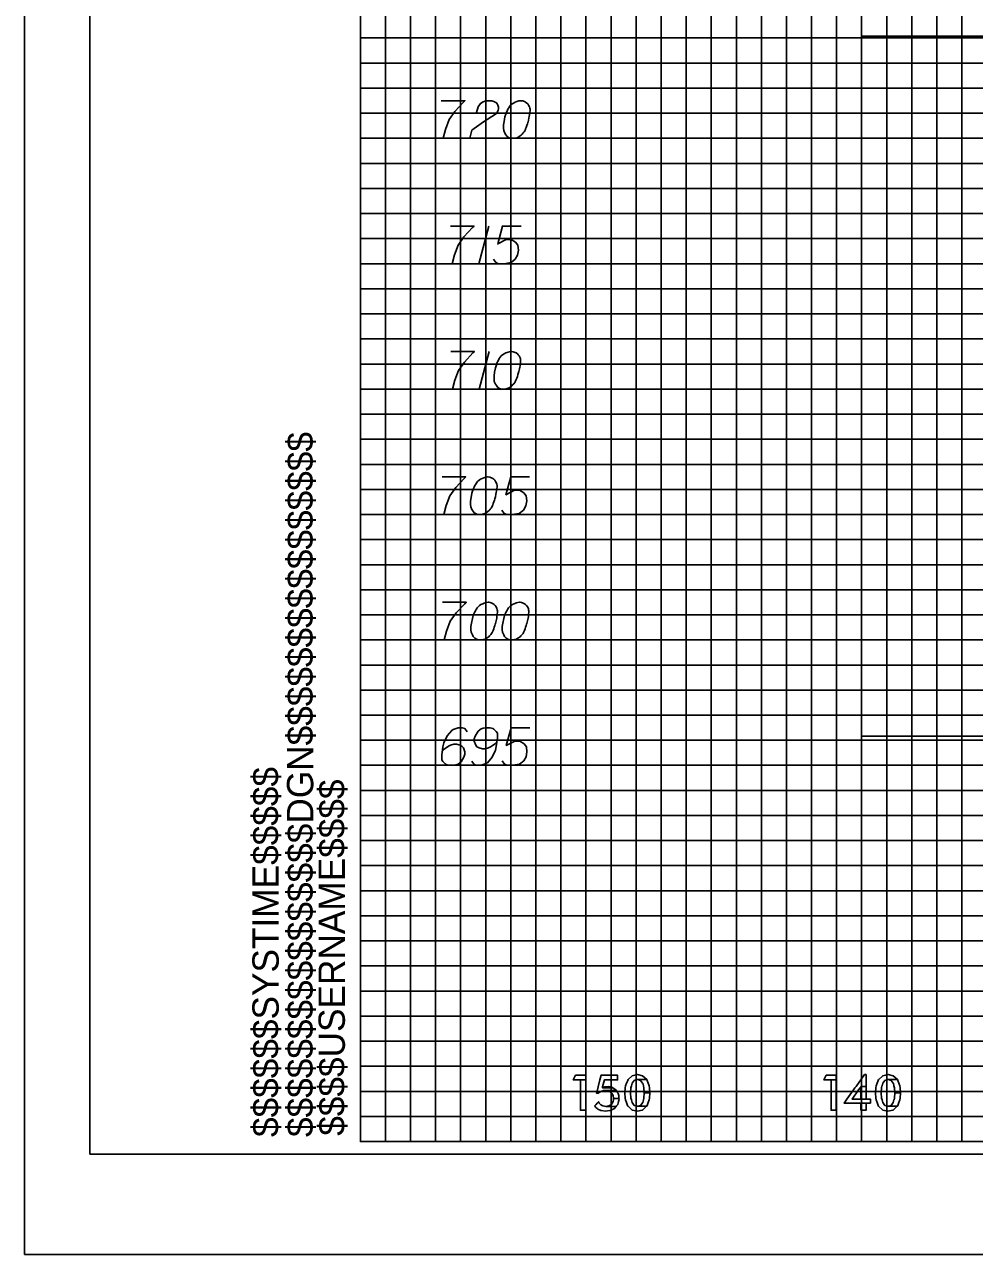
# Model space of a CAD drawing. Extents: x -13 to 323, y -5 to 1431.
# Drawn here: x -13.4 to 24.5, y 655.5 to 704.53 of the extents above; entities that cross this region are included whole.
import ezdxf

# ---------------------------------------------------------------- set-up
doc = ezdxf.new("R2010")
doc.units = 0
for name, color, linetype in [('Prop XS Elevation Labels', 7, 'Continuous'), ('Prop XS Offset Labels', 7, 'Continuous'), ('Scratch_Level_3', 7, 'Continuous'), ('Sheet Cross Section CELL', 7, 'Continuous'), ('Sheet Cross Section Grid Major CELL', 7, 'Continuous'), ('Sheet Cross Section Grid Middle CELL', 7, 'Continuous'), ('Sheet Cross Section Grid Minor 1 CELL', 7, 'Continuous'), ('Sheet Cross Section Grid Minor 2 CELL', 7, 'Continuous'), ('Sheet Cutting Line CELL', 7, 'Continuous'), ('Sheet DOT Grid CELL', 7, 'Continuous'), ('Sheet Plot Border Inside CELL', 7, 'Continuous'), ('Sheet Plot Border Outside CELL', 7, 'Continuous')]:
    doc.layers.add(name, color=color, linetype=linetype)

msp = doc.modelspace()

# ---------------------------------------------------------------- linework, layer by layer
at = {"layer": 'Prop XS Elevation Labels'}
for p, q in [((5.124, 696.5), (4.723, 695)), ((5.142, 691.5), (4.74, 690))]:
    msp.add_line(p, q, dxfattribs=at)
for points in [[(3.228, 701.5), (4.173, 701.5), (4.114, 701.441), (3.772, 701.075), (3.535, 700.744), (3.394, 700.354), (3.299, 700)], [(4.634, 701.028), (4.693, 701.252), (4.787, 701.394), (4.894, 701.453), (5, 701.488), (5.083, 701.5), (5.142, 701.5), (5.248, 701.488), (5.319, 701.465), (5.354, 701.453), (5.425, 701.417), (5.461, 701.37), (5.484, 701.323), (5.496, 701.287), (5.508, 701.24), (5.508, 701.181), (5.496, 701.122), (5.484, 701.087), (5.461, 701.039), (5.425, 700.992), (5.39, 700.957), (4.906, 700.661), (4.445, 700.319), (4.362, 700), (5.437, 700)], [(6.417, 701.5), (6.394, 701.5), (6.323, 701.488), (6.276, 701.476), (6.24, 701.465), (6.181, 701.441), (6.11, 701.406), (6.051, 701.37), (5.992, 701.323), (5.957, 701.276), (5.921, 701.217), (5.886, 701.158), (5.85, 701.087), (5.827, 701.039), (5.803, 700.969), (5.768, 700.85), (5.732, 700.673), (5.709, 700.531), (5.709, 700.402), (5.721, 700.307), (5.768, 700.201), (5.803, 700.142), (5.862, 700.071), (5.933, 700.024), (5.968, 700.012), (6.039, 700), (6.098, 700), (6.193, 700.012), (6.276, 700.035), (6.335, 700.071), (6.417, 700.13), (6.453, 700.165), (6.5, 700.213), (6.535, 700.26), (6.559, 700.295), (6.583, 700.354), (6.594, 700.378), (6.618, 700.437), (6.642, 700.508), (6.665, 700.579), (6.677, 700.626), (6.689, 700.661), (6.701, 700.709), (6.724, 700.815), (6.736, 700.874), (6.748, 700.933), (6.76, 701.016), (6.772, 701.122), (6.772, 701.158), (6.76, 701.205), (6.748, 701.252), (6.713, 701.323), (6.677, 701.37), (6.642, 701.406), (6.594, 701.441), (6.547, 701.465), (6.512, 701.476), (6.476, 701.488), (6.417, 701.5)], [(3.589, 696.5), (4.533, 696.5), (4.474, 696.441), (4.132, 696.075), (3.896, 695.744), (3.754, 695.354), (3.659, 695)], [(6.411, 696.5), (5.667, 696.5), (5.478, 695.791), (5.821, 695.969), (6.022, 695.969), (6.187, 695.862), (6.282, 695.744), (6.305, 695.543), (6.27, 695.342), (6.175, 695.177), (6.01, 695.047), (5.726, 695), (5.514, 695), (5.408, 695.047), (5.313, 695.177)], [(3.606, 691.5), (4.551, 691.5), (4.492, 691.441), (4.149, 691.075), (3.913, 690.744), (3.772, 690.354), (3.677, 690)], [(6.039, 691.5), (6.016, 691.5), (5.945, 691.488), (5.898, 691.476), (5.862, 691.465), (5.803, 691.441), (5.732, 691.406), (5.673, 691.37), (5.614, 691.323), (5.579, 691.276), (5.543, 691.217), (5.508, 691.158), (5.472, 691.087), (5.449, 691.039), (5.425, 690.969), (5.39, 690.85), (5.354, 690.673), (5.331, 690.531), (5.331, 690.402), (5.343, 690.307), (5.39, 690.201), (5.425, 690.142), (5.484, 690.071), (5.555, 690.024), (5.591, 690.012), (5.661, 690), (5.72, 690), (5.815, 690.012), (5.898, 690.035), (5.957, 690.071), (6.039, 690.13), (6.075, 690.165), (6.122, 690.213), (6.157, 690.26), (6.181, 690.295), (6.205, 690.354), (6.217, 690.378), (6.24, 690.437), (6.264, 690.508), (6.287, 690.579), (6.299, 690.626), (6.311, 690.661), (6.323, 690.709), (6.347, 690.815), (6.358, 690.874), (6.37, 690.933), (6.382, 691.016), (6.394, 691.122), (6.394, 691.158), (6.382, 691.205), (6.37, 691.252), (6.335, 691.323), (6.299, 691.37), (6.264, 691.406), (6.217, 691.441), (6.169, 691.465), (6.134, 691.476), (6.098, 691.488), (6.039, 691.5)], [(3.258, 686.5), (4.203, 686.5), (4.144, 686.441), (3.801, 686.075), (3.565, 685.744), (3.423, 685.354), (3.329, 685)], [(5.1, 686.5), (5.077, 686.5), (5.006, 686.488), (4.959, 686.476), (4.923, 686.465), (4.864, 686.441), (4.793, 686.406), (4.734, 686.37), (4.675, 686.323), (4.64, 686.276), (4.604, 686.217), (4.569, 686.158), (4.534, 686.087), (4.51, 686.039), (4.486, 685.969), (4.451, 685.85), (4.415, 685.673), (4.392, 685.531), (4.392, 685.402), (4.404, 685.307), (4.451, 685.201), (4.486, 685.142), (4.545, 685.071), (4.616, 685.024), (4.652, 685.012), (4.723, 685), (4.781, 685), (4.876, 685.012), (4.959, 685.035), (5.018, 685.071), (5.1, 685.13), (5.136, 685.165), (5.183, 685.213), (5.219, 685.26), (5.242, 685.295), (5.266, 685.354), (5.278, 685.378), (5.301, 685.437), (5.325, 685.508), (5.349, 685.579), (5.36, 685.626), (5.372, 685.661), (5.384, 685.709), (5.408, 685.815), (5.419, 685.874), (5.431, 685.933), (5.443, 686.016), (5.455, 686.122), (5.455, 686.158), (5.443, 686.205), (5.431, 686.252), (5.396, 686.323), (5.36, 686.37), (5.325, 686.406), (5.278, 686.441), (5.23, 686.465), (5.195, 686.476), (5.16, 686.488), (5.1, 686.5)], [(6.742, 686.5), (5.998, 686.5), (5.809, 685.791), (6.152, 685.969), (6.352, 685.969), (6.518, 685.862), (6.612, 685.744), (6.636, 685.543), (6.6, 685.342), (6.506, 685.177), (6.341, 685.047), (6.057, 685), (5.845, 685), (5.738, 685.047), (5.644, 685.177)], [(3.276, 681.5), (4.22, 681.5), (4.161, 681.441), (3.819, 681.075), (3.583, 680.744), (3.441, 680.354), (3.346, 680)], [(5.118, 681.5), (5.094, 681.5), (5.024, 681.488), (4.977, 681.476), (4.941, 681.465), (4.882, 681.441), (4.811, 681.406), (4.752, 681.37), (4.693, 681.323), (4.658, 681.276), (4.622, 681.217), (4.587, 681.158), (4.551, 681.087), (4.528, 681.039), (4.504, 680.969), (4.469, 680.85), (4.433, 680.673), (4.409, 680.531), (4.409, 680.402), (4.421, 680.307), (4.469, 680.201), (4.504, 680.142), (4.563, 680.071), (4.634, 680.024), (4.669, 680.012), (4.74, 680), (4.799, 680), (4.894, 680.012), (4.977, 680.035), (5.036, 680.071), (5.118, 680.13), (5.154, 680.165), (5.201, 680.213), (5.236, 680.26), (5.26, 680.295), (5.283, 680.354), (5.295, 680.378), (5.319, 680.437), (5.342, 680.508), (5.366, 680.579), (5.378, 680.626), (5.39, 680.661), (5.402, 680.709), (5.425, 680.815), (5.437, 680.874), (5.449, 680.933), (5.461, 681.016), (5.473, 681.122), (5.473, 681.158), (5.461, 681.205), (5.449, 681.252), (5.413, 681.323), (5.378, 681.37), (5.342, 681.406), (5.295, 681.441), (5.248, 681.465), (5.213, 681.476), (5.177, 681.488), (5.118, 681.5)], [(6.37, 681.5), (6.346, 681.5), (6.276, 681.488), (6.228, 681.476), (6.193, 681.465), (6.134, 681.441), (6.063, 681.406), (6.004, 681.37), (5.945, 681.323), (5.909, 681.276), (5.874, 681.217), (5.838, 681.158), (5.803, 681.087), (5.779, 681.039), (5.756, 680.969), (5.721, 680.85), (5.685, 680.673), (5.661, 680.531), (5.661, 680.402), (5.673, 680.307), (5.721, 680.201), (5.756, 680.142), (5.815, 680.071), (5.886, 680.024), (5.921, 680.012), (5.992, 680), (6.051, 680), (6.146, 680.012), (6.228, 680.035), (6.287, 680.071), (6.37, 680.13), (6.406, 680.165), (6.453, 680.213), (6.488, 680.26), (6.512, 680.295), (6.535, 680.354), (6.547, 680.378), (6.571, 680.437), (6.594, 680.508), (6.618, 680.579), (6.63, 680.626), (6.642, 680.661), (6.653, 680.709), (6.677, 680.815), (6.689, 680.874), (6.701, 680.933), (6.713, 681.016), (6.724, 681.122), (6.724, 681.158), (6.713, 681.205), (6.701, 681.252), (6.665, 681.323), (6.63, 681.37), (6.594, 681.406), (6.547, 681.441), (6.5, 681.465), (6.464, 681.476), (6.429, 681.488), (6.37, 681.5)], [(4.262, 676.335), (4.168, 676.465), (4.061, 676.5), (3.896, 676.5), (3.778, 676.453), (3.707, 676.429), (3.648, 676.394), (3.459, 676.181), (3.329, 675.898), (3.294, 675.744), (3.246, 675.402), (3.246, 675.224), (3.294, 675.154), (3.388, 675.059), (3.423, 675.035), (3.542, 675), (3.695, 675), (3.813, 675.024), (3.896, 675.047), (4.014, 675.142), (4.132, 675.331), (4.168, 675.449), (4.168, 675.543), (4.109, 675.697), (4.061, 675.756), (3.979, 675.803), (3.837, 675.839), (3.73, 675.839), (3.601, 675.803), (3.518, 675.768), (3.376, 675.673), (3.305, 675.614), (3.27, 675.579)], [(4.451, 675.165), (4.545, 675.035), (4.652, 675), (4.817, 675), (4.935, 675.047), (5.006, 675.071), (5.065, 675.106), (5.254, 675.319), (5.384, 675.602), (5.419, 675.756), (5.467, 676.098), (5.467, 676.276), (5.419, 676.346), (5.325, 676.441), (5.289, 676.465), (5.171, 676.5), (5.018, 676.5), (4.9, 676.476), (4.817, 676.453), (4.699, 676.358), (4.581, 676.169), (4.545, 676.051), (4.545, 675.957), (4.604, 675.803), (4.652, 675.744), (4.734, 675.697), (4.876, 675.661), (4.982, 675.661), (5.112, 675.697), (5.195, 675.732), (5.337, 675.827), (5.408, 675.886), (5.443, 675.921)], [(6.754, 676.5), (6.01, 676.5), (5.821, 675.791), (6.163, 675.969), (6.364, 675.969), (6.529, 675.862), (6.624, 675.744), (6.647, 675.543), (6.612, 675.342), (6.517, 675.177), (6.352, 675.047), (6.069, 675), (5.856, 675), (5.75, 675.047), (5.655, 675.177)]]:
    msp.add_lwpolyline(points, dxfattribs=at)
at = {"layer": 'Prop XS Offset Labels'}
for points in [[(8.581, 662.641), (8.492, 662.459), (8.99, 662.459), (8.99, 662.641)], [(8.781, 662.459), (8.781, 661.25), (8.99, 661.25), (8.99, 662.459)], [(9.427, 661.94), (9.424, 661.928), (9.495, 661.928), (9.508, 661.94), (9.524, 661.954), (9.595, 661.997), (9.627, 662.007), (9.697, 662.029), (9.811, 662.035), (10.219, 662.035), (10.211, 662.05), (10.076, 662.145), (9.655, 662.145), (9.658, 662.158), (9.658, 662.158), (9.663, 662.178), (9.738, 662.456), (10.263, 662.456), (10.263, 662.641), (9.6, 662.641), (9.554, 662.456), (9.486, 662.178), (9.481, 662.158), (9.478, 662.145), (9.454, 662.05), (9.451, 662.035), (9.449, 662.029), (9.444, 662.007), (9.441, 661.997), (9.431, 661.954)], [(10.851, 661.255), (11.051, 661.214), (11.245, 661.255), (11.256, 661.257), (11.422, 661.409), (11.047, 661.409), (11.038, 661.411), (11.033, 661.413), (10.928, 661.442), (10.841, 661.555), (10.841, 661.556), (10.841, 661.556), (10.813, 661.657), (10.813, 661.659), (10.793, 661.732), (10.792, 661.736), (10.774, 661.939), (10.774, 661.941), (10.774, 661.943), (10.792, 662.145), (10.812, 662.222), (10.813, 662.224), (10.839, 662.322), (10.84, 662.325), (10.928, 662.44), (11.041, 662.469), (11.045, 662.47), (11.055, 662.473), (11.425, 662.473), (11.262, 662.622), (11.254, 662.624), (11.053, 662.668), (11.053, 662.668), (10.845, 662.624), (10.843, 662.622), (10.681, 662.473), (10.678, 662.47), (10.678, 662.469), (10.665, 662.44), (10.618, 662.325), (10.617, 662.322), (10.577, 662.224), (10.576, 662.222), (10.568, 662.145), (10.547, 661.943), (10.547, 661.941), (10.547, 661.939), (10.567, 661.736), (10.568, 661.732), (10.575, 661.659), (10.575, 661.657), (10.616, 661.556), (10.617, 661.555), (10.663, 661.442), (10.675, 661.413), (10.676, 661.411), (10.679, 661.409), (10.848, 661.257)], [(11.312, 662.145), (11.328, 661.943), (11.555, 661.943), (11.536, 662.145), (11.528, 662.222), (11.527, 662.224), (11.527, 662.224), (11.488, 662.322), (11.488, 662.322), (11.487, 662.325), (11.441, 662.44), (11.44, 662.44), (11.429, 662.469), (11.428, 662.47), (11.425, 662.473), (11.055, 662.473), (11.065, 662.47), (11.068, 662.469), (11.175, 662.44), (11.262, 662.325), (11.265, 662.322), (11.291, 662.224), (11.291, 662.222)], [(18.581, 662.641), (18.492, 662.459), (18.99, 662.459), (18.99, 662.641)], [(18.781, 662.459), (18.781, 661.25), (18.99, 661.25), (18.99, 662.459)], [(19.411, 661.693), (19.297, 661.534), (20.35, 661.534), (20.35, 661.693), (19.618, 661.693), (19.878, 662.059), (19.935, 662.139), (19.977, 662.199), (20.179, 662.199), (20.179, 662.668), (20.114, 662.668), (19.775, 662.199), (19.733, 662.139), (19.675, 662.059)], [(20.851, 661.255), (21.051, 661.214), (21.245, 661.255), (21.256, 661.257), (21.422, 661.409), (21.047, 661.409), (21.038, 661.411), (21.033, 661.413), (20.928, 661.442), (20.841, 661.555), (20.841, 661.556), (20.841, 661.556), (20.813, 661.657), (20.813, 661.659), (20.793, 661.732), (20.792, 661.736), (20.774, 661.939), (20.774, 661.941), (20.774, 661.943), (20.792, 662.145), (20.812, 662.222), (20.813, 662.224), (20.839, 662.322), (20.84, 662.325), (20.928, 662.44), (21.041, 662.469), (21.045, 662.47), (21.055, 662.473), (21.425, 662.473), (21.262, 662.622), (21.254, 662.624), (21.053, 662.668), (21.053, 662.668), (20.845, 662.624), (20.843, 662.622), (20.681, 662.473), (20.678, 662.47), (20.678, 662.469), (20.665, 662.44), (20.618, 662.325), (20.617, 662.322), (20.577, 662.224), (20.576, 662.222), (20.568, 662.145), (20.547, 661.943), (20.547, 661.941), (20.547, 661.939), (20.567, 661.736), (20.567, 661.732), (20.575, 661.659), (20.575, 661.657), (20.616, 661.556), (20.617, 661.555), (20.663, 661.442), (20.675, 661.413), (20.676, 661.411), (20.679, 661.409), (20.848, 661.257)], [(21.312, 662.145), (21.328, 661.943), (21.555, 661.943), (21.536, 662.145), (21.528, 662.222), (21.527, 662.224), (21.527, 662.224), (21.488, 662.322), (21.488, 662.322), (21.487, 662.325), (21.441, 662.44), (21.44, 662.44), (21.429, 662.469), (21.428, 662.47), (21.425, 662.473), (21.055, 662.473), (21.065, 662.47), (21.068, 662.469), (21.175, 662.44), (21.262, 662.325), (21.265, 662.322), (21.291, 662.224), (21.291, 662.222)], [(9.692, 662.158), (9.655, 662.145), (10.076, 662.145), (10.058, 662.158), (9.961, 662.178), (9.75, 662.178)], [(9.888, 662.192), (9.75, 662.178), (9.96, 662.178), (9.888, 662.192)], [(10.083, 661.841), (10.105, 661.721), (10.318, 661.721), (10.307, 661.841), (10.307, 661.841), (10.303, 661.881), (10.284, 661.916), (10.278, 661.928), (10.271, 661.94), (10.263, 661.954), (10.24, 661.997), (10.235, 662.007), (10.223, 662.029), (10.219, 662.035), (9.811, 662.035), (9.838, 662.029), (9.928, 662.007), (9.943, 661.997), (10.003, 661.954), (10.024, 661.94), (10.031, 661.928), (10.038, 661.916), (10.059, 661.881)], [(19.97, 662.059), (19.97, 661.693), (20.179, 661.693), (20.179, 662.059), (20.179, 662.139), (20.179, 662.199), (19.977, 662.199), (19.973, 662.139)], [(9.626, 661.233), (9.762, 661.214), (9.959, 661.233), (9.968, 661.237), (10.091, 661.297), (10.091, 661.297), (10.141, 661.321), (10.185, 661.375), (10.204, 661.399), (9.793, 661.399), (9.683, 661.418), (9.682, 661.419), (9.679, 661.42), (9.596, 661.466), (9.586, 661.477), (9.58, 661.483), (9.58, 661.483), (9.529, 661.535), (9.497, 661.585), (9.497, 661.585), (9.451, 661.535), (9.404, 661.483), (9.399, 661.477), (9.39, 661.466), (9.348, 661.42), (9.347, 661.419), (9.348, 661.418), (9.363, 661.399), (9.382, 661.375), (9.445, 661.321), (9.474, 661.297), (9.598, 661.237)], [(9.424, 661.928), (9.482, 661.916), (9.495, 661.928)], [(9.9, 661.418), (9.793, 661.399), (10.204, 661.399), (10.22, 661.418), (10.221, 661.419), (10.222, 661.42), (10.222, 661.42), (10.259, 661.466), (10.268, 661.477), (10.27, 661.483), (10.284, 661.535), (10.299, 661.59), (10.322, 661.674), (10.318, 661.721), (10.105, 661.721), (10.097, 661.674), (10.082, 661.59), (10.047, 661.535), (10.014, 661.483), (10.004, 661.477), (9.987, 661.466), (9.913, 661.42), (9.905, 661.419)], [(11.058, 661.411), (11.047, 661.409), (11.422, 661.409), (11.425, 661.411), (11.426, 661.413), (11.438, 661.442), (11.485, 661.555), (11.485, 661.556), (11.527, 661.657), (11.528, 661.659), (11.535, 661.732), (11.535, 661.736), (11.555, 661.939), (11.556, 661.941), (11.555, 661.943), (11.328, 661.943), (11.328, 661.941), (11.328, 661.939), (11.312, 661.736), (11.312, 661.732), (11.292, 661.659), (11.291, 661.657), (11.264, 661.556), (11.263, 661.555), (11.175, 661.442), (11.063, 661.413)], [(19.97, 661.534), (19.97, 661.25), (20.179, 661.25), (20.179, 661.534)], [(21.058, 661.411), (21.047, 661.409), (21.422, 661.409), (21.425, 661.411), (21.426, 661.413), (21.438, 661.442), (21.485, 661.555), (21.485, 661.556), (21.527, 661.657), (21.528, 661.659), (21.535, 661.732), (21.535, 661.736), (21.555, 661.939), (21.556, 661.941), (21.555, 661.943), (21.328, 661.943), (21.328, 661.941), (21.328, 661.939), (21.312, 661.736), (21.312, 661.732), (21.292, 661.659), (21.291, 661.657), (21.264, 661.556), (21.263, 661.555), (21.175, 661.442), (21.063, 661.413)]]:
    msp.add_lwpolyline(points, close=True, dxfattribs=at)
at = {"layer": 'Scratch_Level_3'}
msp.add_lwpolyline([(20, 704.068), (300, 704.068), (300, 676.157), (20, 676.157)], close=True, dxfattribs=at)
at = {"layer": 'Sheet Cross Section CELL'}
msp.add_line((0, 660), (0, 660), dxfattribs=at)
msp.add_line((0, 660), (0, 660), dxfattribs=at)
msp.add_line((0, 660), (0, 660), dxfattribs=at)
msp.add_line((0, 660), (0, 660), dxfattribs=at)
msp.add_line((0, 660), (0, 660), dxfattribs=at)
msp.add_line((0, 660), (0, 660), dxfattribs=at)
msp.add_line((0, 660), (0, 660), dxfattribs=at)
msp.add_lwpolyline([(320, 870), (0, 870), (0, 660), (320, 660)], close=True, dxfattribs=at)
at = {"layer": 'Sheet Cross Section Grid Major CELL'}
for p, q in [((10, 660), (10, 870)), ((20, 870), (20, 660)), ((20, 660), (10, 660))]:
    msp.add_line(p, q, dxfattribs=at)
for points in [[(0, 700), (320, 700), (320, 690), (0, 690)], [(0, 680), (320, 680), (320, 670), (0, 670)]]:
    msp.add_lwpolyline(points, dxfattribs=at)
at = {"layer": 'Sheet Cross Section Grid Middle CELL'}
for points in [[(5, 870), (5, 660), (15, 660), (15, 870)], [(0, 685), (320, 685), (320, 695), (0, 695)], [(0, 665), (320, 665), (320, 675), (0, 675)]]:
    msp.add_lwpolyline(points, dxfattribs=at)
at = {"layer": 'Sheet Cross Section Grid Minor 1 CELL'}
for points in [[(0, 704), (320, 704), (320, 703), (0, 703)], [(0, 702), (320, 702), (320, 701), (0, 701)], [(0, 699), (320, 699), (320, 698), (0, 698)], [(0, 697), (320, 697), (320, 696), (0, 696)], [(0, 694), (320, 694), (320, 693), (0, 693)], [(0, 692), (320, 692), (320, 691), (0, 691)], [(0, 689), (320, 689), (320, 688), (0, 688)], [(0, 687), (320, 687), (320, 686), (0, 686)], [(0, 684), (320, 684), (320, 683), (0, 683)], [(0, 682), (320, 682), (320, 681), (0, 681)], [(0, 679), (320, 679), (320, 678), (0, 678)], [(0, 677), (320, 677), (320, 676), (0, 676)], [(0, 674), (320, 674), (320, 673), (0, 673)], [(0, 672), (320, 672), (320, 671), (0, 671)], [(0, 669), (320, 669), (320, 668), (0, 668)], [(0, 667), (320, 667), (320, 666), (0, 666)], [(0, 664), (320, 664), (320, 663), (0, 663)], [(0, 662), (320, 662), (320, 661), (0, 661)]]:
    msp.add_lwpolyline(points, dxfattribs=at)
at = {"layer": 'Sheet Cross Section Grid Minor 2 CELL'}
for points in [[(0, 660), (1, 660), (1, 870), (2, 870), (2, 660)], [(2, 660), (3, 660), (3, 870), (4, 870), (4, 660)], [(5, 660), (6, 660), (6, 870), (7, 870), (7, 660)], [(7, 660), (8, 660), (8, 870), (9, 870), (9, 660)], [(10, 660), (11, 660), (11, 870), (12, 870), (12, 660)], [(12, 660), (13, 660), (13, 870), (14, 870), (14, 660)], [(15, 660), (16, 660), (16, 870), (17, 870), (17, 660)], [(17, 660), (18, 660), (18, 870), (19, 870), (19, 660)], [(20, 660), (21, 660), (21, 870), (22, 870), (22, 660)], [(22, 660), (23, 660), (23, 870), (24, 870), (24, 660)]]:
    msp.add_lwpolyline(points, dxfattribs=at)
at = {"layer": 'Sheet Cutting Line CELL'}
for p, q in [((-13.4, 874.5), (-13.4, 655.5)), ((-13.4, 655.5), (323.3, 655.5))]:
    msp.add_line(p, q, dxfattribs=at)
at = {"layer": 'Sheet DOT Grid CELL'}
for p, q in [((10, 660), (10, 870)), ((20, 660), (20, 870)), ((0, 700), (320, 700)), ((0, 690), (320, 690)), ((0, 680), (320, 680)), ((0, 670), (320, 670))]:
    msp.add_line(p, q, dxfattribs=at)
at = {"layer": 'Sheet Plot Border Inside CELL'}
msp.add_lwpolyline([(-10.8, 659.5), (322.4, 659.5), (322.4, 870.5), (-10.8, 870.5)], close=True, dxfattribs=at)
at = {"layer": 'Sheet Plot Border Outside CELL'}
msp.add_lwpolyline([(-13.4, 655.5), (323.3, 655.5), (323.3, 874.5), (-13.4, 874.5)], close=True, dxfattribs=at)

# ---------------------------------------------------------------- texts
at = {"layer": 'Sheet Cross Section CELL'}
for s, p in [('$$$$$$$$$$$$$$$$DGN$$$$$$$$$$$$$$$$', (-1.88, 660.18)), ('$$$$$$SYSTIME$$$$$', (-3.26, 660.18)), ('$$$$USERNAME$$$$', (-0.62, 660.23))]:
    msp.add_text(s, height=1.05, rotation=90, dxfattribs=at).set_placement(p)

doc.saveas('drawing.dxf')
